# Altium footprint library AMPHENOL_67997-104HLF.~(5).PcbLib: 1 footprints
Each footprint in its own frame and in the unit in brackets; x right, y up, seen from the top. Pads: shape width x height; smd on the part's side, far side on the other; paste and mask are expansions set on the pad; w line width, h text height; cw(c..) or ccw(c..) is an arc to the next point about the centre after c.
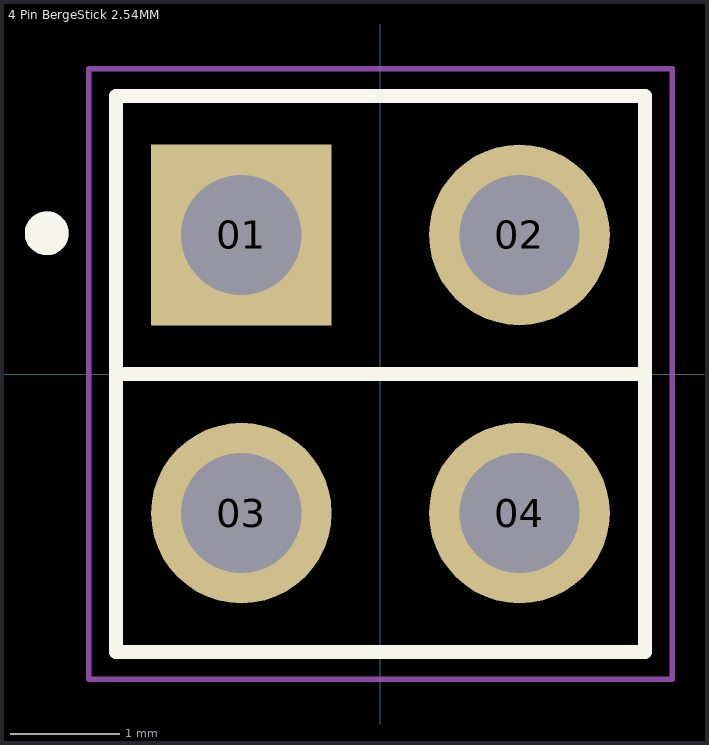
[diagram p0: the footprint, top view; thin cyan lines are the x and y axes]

## 4 Pin BergeStick 2.54MM [mm] "4 Pin 2X2Pos THT BergeStick 2.54MM Amphenol 67997-104HLF 3A AMPHENOL_67997-104HLF"
pads (4):
  rect 1.65x1.65 / inner round 1.65 / far side rect 1.65x1.65 hole 1.1: 01(-1.27,1.27)
  round 1.65 hole 1.1: 02(1.27,1.27) 03(-1.27,-1.27) 04(1.27,-1.27)
Top Overlay:
  circle w0.2: c-3.048,1.285 r0.1
  lines w0.127: -2.413,0 2.413,0 ; -2.415,-2.54 -2.415,2.54 2.415,2.54 2.415,-2.54 -2.415,-2.54
Mechanical 13:
  circle w0.2: c-3.048,1.285 r0.1
  lines w0.127: -2.413,0 2.413,0 ; -2.415,-2.54 2.415,-2.54 ; -2.415,-2.54 -2.415,2.54 ; -2.415,-2.54 2.415,-2.54 ; -2.415,2.54 2.415,2.54 ; -2.415,2.54 2.415,2.54 ; 2.415,-2.54 2.415,2.54 ; 2.415,-2.54 2.415,2.54
Mechanical 15:
  lines w0.05: -2.665,-2.79 -2.665,2.79 2.665,2.79 2.665,-2.79 -2.665,-2.79
3D body "step_temp.STEP": height 8.38, standoff -3.05, extent -2.415,-2.54 2.415,2.54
